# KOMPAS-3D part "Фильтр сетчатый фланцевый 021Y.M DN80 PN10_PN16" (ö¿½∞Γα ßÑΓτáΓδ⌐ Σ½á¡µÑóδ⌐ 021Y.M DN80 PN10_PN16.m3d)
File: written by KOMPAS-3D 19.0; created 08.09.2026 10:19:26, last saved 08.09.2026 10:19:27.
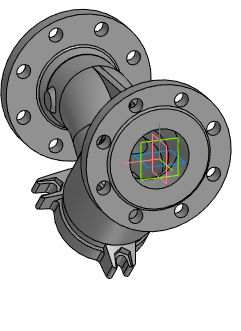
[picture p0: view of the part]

Document properties: Автор: user; Полное имя файла: Z:\3.Личные\sachek\Dendor\_3D для проектировщиков\8.2 Фильтр сетчатый 021Y.M\021Y.M_STP\Фильтр сетчатый фланцевый 021Y.M DN80 PN10_PN16.m3d

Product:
- Part/product: Фильтр сетчатый фланцевый 021Y.M DN80 PN10_PN16
    Масса: 18.5227

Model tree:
1. Операция без истории:1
